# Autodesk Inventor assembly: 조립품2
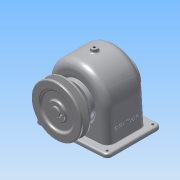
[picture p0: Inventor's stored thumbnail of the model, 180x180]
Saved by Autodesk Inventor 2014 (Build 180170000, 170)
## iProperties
Created: 2016-01
Part Number: 조립품2
Document SubType Name: Assembly
Designer: User
Author: User
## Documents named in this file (16)
- C:\Documents and Settings\User\My Documents\Inventor\460106V1016\조립품.iam
- C:\Documents and Settings\User\My Documents\Inventor\460106V1016\본체.ipt
- C:\Documents and Settings\User\My Documents\Inventor\460106V1016\축.ipt
- C:\Documents and Settings\User\My Documents\Inventor\460106V1016\뒤커버.ipt
- C:\Documents and Settings\User\My Documents\Inventor\460106V1016\베어링 6203.ipt
- C:\Documents and Settings\User\My Documents\Inventor\460106V1016\오일씰 28 40 8.ipt
- C:\Documents and Settings\User\My Documents\Inventor\460106V1016\부시1.ipt
- C:\Documents and Settings\User\My Documents\Inventor\460106V1016\부시2.ipt
- C:\Documents and Settings\User\My Documents\Inventor\460106V1016\스퍼기어.ipt
- C:\Documents and Settings\User\My Documents\Inventor\460106V1016\키 - 6 x 6 x 22.ipt
- C:\Documents and Settings\User\My Documents\Inventor\460106V1016\키 - 5 x 5 x 18.ipt
- C:\Documents and Settings\User\My Documents\Inventor\460106V1016\앞커버.ipt
- C:\Documents and Settings\User\My Documents\Inventor\460106V1016\V-벨트풀리.ipt
- C:\Documents and Settings\User\My Documents\Inventor\460106V1016\멈춤나사 - M4x10.ipt
- C:\Documents and Settings\User\My Documents\Inventor\460106V1016\볼트 M3 x 10.ipt
- C:\Documents and Settings\User\My Documents\Inventor\460106V1016\볼트 M3 x 8.ipt
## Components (9 placed, 3 different names)
1. V-벨트풀리:1
2. ISO 4762 M3 x 8:1
3. ISO 4762 M3 x 10:1
4. ISO 4762 M3 x 8:2
5. ISO 4762 M3 x 10:2
6. ISO 4762 M3 x 8:3
7. ISO 4762 M3 x 10:3
8. ISO 4762 M3 x 8:4
9. ISO 4762 M3 x 10:4
